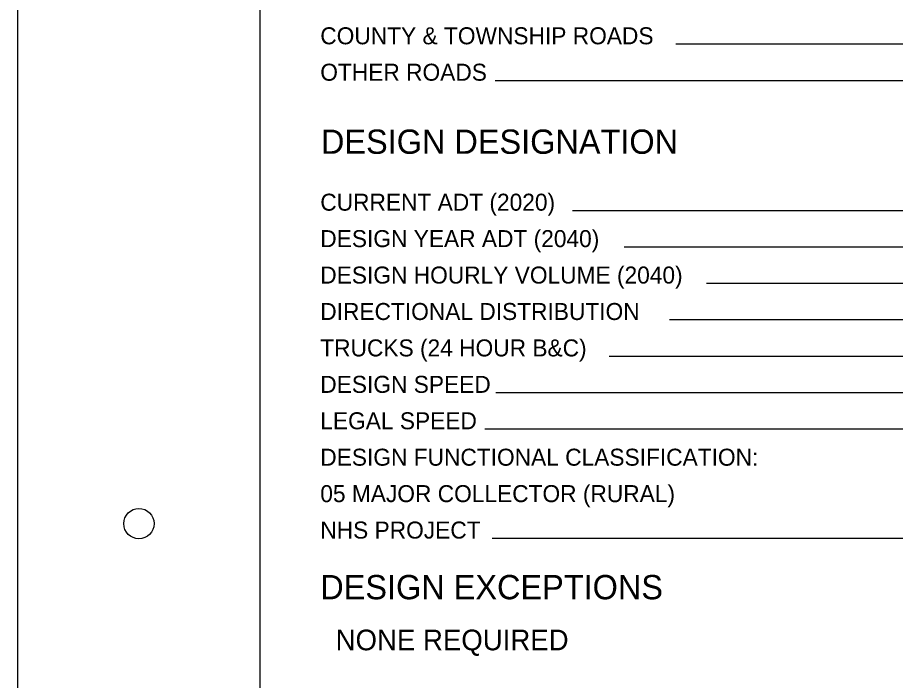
# Model space of a CAD drawing. Extents: x 0 to 34, y 0 to 22.
# Drawn here: x 0 to 7.23, y 5.46 to 10.92 of the extents above; entities that cross this region are included whole.
import ezdxf

# ---------------------------------------------------------------- set-up
doc = ezdxf.new("R2010")
doc.units = 0
for name, color, linetype in [('SH_Border', 7, 'Continuous'), ('SH_Cut_Line', 7, 'Continuous'), ('SH_Data', 7, 'Continuous')]:
    doc.layers.add(name, color=color, linetype=linetype)

msp = doc.modelspace()

# ---------------------------------------------------------------- linework, layer by layer
at = {"layer": 'SH_Border'}
msp.add_lwpolyline([(2, 21.5), (33.5, 21.5), (33.5, 0.5), (2, 0.5)], close=True, dxfattribs=at)
msp.add_circle((1, 6.75), 0.125, dxfattribs=at)
at = {"layer": 'SH_Cut_Line'}
msp.add_lwpolyline([(0, 0), (34, 0), (34, 22), (0, 22)], close=True, dxfattribs=at)
at = {"layer": 'SH_Data'}
for p, q in [((8.2, 10.6975), (5.424, 10.6975)), ((8.2, 10.3975), (3.9348, 10.3975)), ((8.1424, 9.3271), (4.5737, 9.3271)), ((8.1368, 9.0271), (4.9987, 9.0271)), ((8.1368, 8.7271), (5.6758, 8.7271)), ((8.1368, 8.4271), (5.3711, 8.4271)), ((8.1368, 8.1271), (4.8746, 8.1271)), ((8.1368, 7.8271), (3.9417, 7.8271)), ((8.1368, 7.5271), (3.8514, 7.5271)), ((8.1368, 6.6271), (3.9116, 6.6271))]:
    msp.add_line(p, q, dxfattribs=at)

# ---------------------------------------------------------------- texts
for s, height, p in [('COUNTY & TOWNSHIP ROADS', 0.14, (2.4944, 10.6975)), ('OTHER ROADS', 0.14, (2.4944, 10.3975)), ('DESIGN DESIGNATION', 0.2, (2.5, 9.7955)), ('CURRENT ADT (2020)', 0.14, (2.4944, 9.3271)), ('DESIGN YEAR ADT (2040)', 0.14, (2.4944, 9.0271)), ('DESIGN HOURLY VOLUME (2040)', 0.14, (2.4944, 8.7271)), ('DIRECTIONAL DISTRIBUTION', 0.14, (2.4944, 8.4271)), ('TRUCKS (24 HOUR B&C)', 0.14, (2.4944, 8.1271)), ('DESIGN SPEED', 0.14, (2.4944, 7.8271)), ('LEGAL SPEED', 0.14, (2.4944, 7.5271)), ('DESIGN FUNCTIONAL CLASSIFICATION:', 0.14, (2.4944, 7.2271)), ('05 MAJOR COLLECTOR (RURAL)', 0.14, (2.4944, 6.9271)), ('NHS PROJECT', 0.14, (2.4944, 6.6271)), ('DESIGN EXCEPTIONS', 0.2, (2.4944, 6.1271)), ('  NONE REQUIRED', 0.17, (2.4944, 5.7071))]:
    msp.add_text(s, height=height, dxfattribs=at).set_placement(p)

doc.saveas('drawing.dxf')
